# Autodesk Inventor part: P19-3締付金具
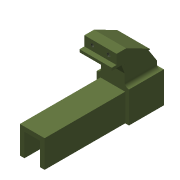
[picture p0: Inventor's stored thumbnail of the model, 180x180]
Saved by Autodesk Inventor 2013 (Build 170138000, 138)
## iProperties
Created: 2008-07
Part Number: P19-3締付金具
Document SubType Name: Modeling
Designer: y-shimohigashi
Density: 1 g/cm^3
Stock Number: P19-3締付金具
Material: 一般
Author: y-shimohigashi
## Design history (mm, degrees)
sketch "スケッチ3"
  geometry: L1 (43, 22)-(43, 80); L2 (43, 80)-(38, 80); L3 (38, 80)-(38, 93); L4 (38, 93)-(16, 127); L5 (16, 127)-(-27, 149); L6 (-27, 149)-(-45, 149); L7 (-45, 149)-(-45, 131); L8 (-45, 131)-(-54, 131); L9 (-54, 131)-(-54, 126); L10 (-54, 126)-(-44, 126); L11 (-44, 126)-(-31, 126); L12 (-31, 126)-(-22, 102); L13 (-22, 102)-(-22, 22); L14 (-22, 22)-(43, 22); 1 further point
  constraints: 28 end point, 6 parallel, 1 horizontal, 1 perpendicular, 1 vertical
  dimensions: "d4" = 58 distance of L1.start L1.end; "d5" = 13 distance of L2.end L3.end; "d6" = 34 vertical distance of L3.end L4.end; "d7" = 22 vertical distance of L4.end L5.end; "d8" = 5 distance of L1.end L2.end; "d9" = 22 horizontal distance of L3.end L4.end; "d10" = 43 horizontal distance of L4.end L5.end; "d11" = 18 distance of L5.end L6.end; "d12" = 9 distance of L7.end L8.end; "d13" = 18 distance of L6.end L7.end; "d14" = 5 distance of L8.end L9.end; "d15" = 10 distance of L9.end L10.end; "d16" = 24 vertical distance of L11.end L12.end; "d17" = 80 distance of L12.end L13.end; "d18" = 65 distance between parallel lines of L1 L13; "d19" = 13 distance of L10.end L11.end; "d66" = 43 distance from line of L1 point (0, 0); "d67" = 22 distance from line of point (0, 0) L14
extrude "押し出し2" new body sketch "スケッチ3" stored distance "d20" = 60; taper "d21" = 0 deg
sketch "スケッチ4"
  geometry: L1 (0, 0)-(60, 0) reference; L2 (60, 0)-(52, 0); L3 (52, 0)-(52, -45); L4 (52, -45)-(60, -45); L5 (60, -45)-(60, 0); L6 (0, 0)-(8, 0); L7 (8, 0)-(8, -45); L8 (8, -45)-(0, -45); L9 (0, -45)-(0, 0)
  constraints: 16 end point, 4 parallel, 2 collinear, 2 horizontal, 2 perpendicular
  dimensions: "d22" = 8 distance of L3.end L4.end; "d23" = 45 distance of L4.end L1.end
extrude "押し出し3" cut sketch "スケッチ4" stored distance "d24" = 60; taper "d25" = 0 deg
sketch "スケッチ9"
  geometry: L1 (-60, 58)-(-60, 0) reference; L2 (-60, 0)-(0, 0) reference; L3 (0, 0)-(0, 58) reference; L4 (0, 58)-(-60, 58) reference; L5 (-53, 51)-(-53, 0); L6 (-7, 0)-(-7, 51); L7 (-7, 51)-(-53, 51); L8 (-53, 0)-(-44.5, 0); L9 (-44.5, 42.5)-(-15.5, 42.5); L10 (-15.5, 42.5)-(-15.5, 0); L11 (-44.5, 42.5)-(-44.5, 0); L12 (-15.5, 0)-(-7, 0)
  constraints: 16 end point, 4 point on line, 2 parallel, 2 perpendicular, 1 collinear
  dimensions: "d68" = 7 distance between parallel lines of L7 L4; "d69" = 7 distance between parallel lines of L5 L1 (= d68); "d70" = 7 distance between parallel lines of L3 L6 (= d68); "d71" = 8.5 distance between parallel lines of L9 L7; "d72" = 8.5 distance between parallel lines of L11 L5 (= d71)
extrude "押し出し6" join sketch "スケッチ9" distance "d74" = 215; taper "d75" = 0 deg
sketch "スケッチ10"
  geometry: L1 (60, 0)-(0, 0) reference; 2 further points
  constraints: 1 midpoint, 1 vertical alignment
  dimensions: "d85" = 25.5 distance from line of L1 point (30, -25.5)
hole "穴4" sketch "スケッチ10" at (30, -25.5) diameter "d76" = 16; stored, may be unused: countersink angle "d80" = 90 deg, drill point angle "d82" = 118 deg; dims "d77" = 6, "d78" = 36, "d79" = 15, "d81" = 8
feature "ねじ1" dims "d83" = 10, "d84" = 0
sketch "スケッチ11"
  geometry: L1 (30, -152.4)-(30, 25.4) reference; L2 (60, -18)-(60, 0) reference; 3 further points
  constraints: 2 horizontal alignment, 1 midpoint, 1 symmetric about line
  dimensions: "d88" = 30 distance of point (45, -9) point (15, -9)
hole "穴5" sketch "スケッチ11" at (15, -9), (45, -9) diameter "d89" = 6.647; stored, may be unused: countersink angle "d93" = 90 deg, drill point angle "d95" = 118 deg; dims "d90" = 6, "d91" = 36, "d92" = 15, "d94" = 8
fillet "フィレット4" dims "d96" = 8
node "ソリッド1"
node "ソリッド ボディ"
node "サーフェス ボディ"
node "投影ループ2"
